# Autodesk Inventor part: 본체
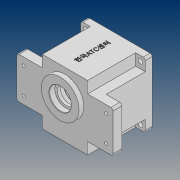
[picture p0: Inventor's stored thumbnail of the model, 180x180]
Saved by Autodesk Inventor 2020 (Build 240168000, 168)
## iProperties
Created: 2020-07
Part Number: 본체
Material: 일반
Document SubType Name: Modeling
Designer: PC312-
Density: 1 g/cm^3
Appearance: 기본값
Author: PC312-
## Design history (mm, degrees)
sketch "스케치1"
  geometry: L1 (-47, 47)-(47, 47); L2 (47, 47)-(47, -47); L3 (47, -47)-(-47, -47); L4 (-47, -47)-(-47, 47); L5 (-47, 47)-(47, -47); L6 (47, 47)-(-47, -47); 1 further point
  constraints: 12 end point, 2 midpoint, 2 parallel, 1 horizontal, 1 perpendicular
  dimensions: "d0" = 94 distance of L2.end L3.end; "d1" = 94 distance of L1.end L2.end
extrude "돌출1" new body sketch "스케치1" stored distance "d2" = 80; taper "d3" = 0 deg
sketch "스케치2"
  geometry: C1 r 27.5 at (0, 11); 1 further point
  constraints: 1 centre point, 1 vertical alignment
  dimensions: "d4" = 55 diameter of C1; "d5" = 11 distance of point (0, 0) C1.centre
extrude "돌출2" join sketch "스케치2" distance "d6" = 7; taper "d7" = 0 deg
sketch "스케치3"
  geometry: L1 (-70, 30)-(70, 30); L2 (70, 30)-(70, -30); L3 (70, -30)-(-70, -30); L4 (-70, -30)-(-70, 30); L5 (-70, 30)-(70, -30); L6 (70, 30)-(-70, -30); 1 further point
  constraints: 12 end point, 2 midpoint, 2 parallel, 1 horizontal, 1 perpendicular
  dimensions: "d8" = 140 distance of L2.end L3.end; "d9" = 60 distance of L1.end L2.end
extrude "돌출3" join sketch "스케치3" distance "d10" = 13; taper "d11" = 0 deg
sketch "스케치4"
  geometry: L1 (47, 47)-(-47, 47) reference; L2 (33, 47)-(33, 30); L3 (47, 30)-(47, -30) reference; L4 (33, 30)-(47, 30); L5 (47, 30)-(47, 47) reference; L6 (33, 47)-(47, 47); L7 (47, 47)-(47, 29.432); 1 further point
  constraints: 8 end point, 2 point on line, 1 horizontal, 1 vertical
  dimensions: "d12" = 17 distance of L2.start L2.end; "d14" = 14 distance of L2.end L3.start
extrude "돌출4" cut sketch "스케치4" distance "d15" = 70; taper "d16" = 0 deg
sketch "스케치5"
  geometry: C1 r 3.5 at (-40, -40); C2 r 3.5 at (40, -40); C3 r 3.5 at (-40, 40); C4 r 3.5 at (40, 40); 1 further point
  constraints: 4 centre point
  dimensions: "d17" = 7 diameter of C1; "d18" = 7 diameter of C2; "d19" = 7 diameter of C3; "d20" = 7 diameter of C4; "d21" = 80 distance of C2.centre C4.centre; "d22" = 80 distance of C1.centre C3.centre; "d23" = 80 distance of C4.centre C3.centre; "d24" = 80 distance of C2.centre C1.centre; "d25" = 40 horizontal distance of C4.centre point (0, 0); "d26" = 40 horizontal distance of point (0, 0) C3.centre; "d27" = 40 horizontal distance of C2.centre point (0, 0); "d28" = 40 horizontal distance of C2.centre point (0, 0)
extrude "돌출5" cut sketch "스케치5" extent not by distance; stored distance "d29" = 0; taper "d30" = 0 deg
sketch "스케치6"
  geometry: 3 further points
  constraints: 1 vertical alignment
  dimensions: "d31" = 38 distance of point (-60, 19) point (-60, -19); "d32" = 19 vertical distance of point (-60, -19) point (0, 0); "d33" = 60 horizontal distance of point (-60, -19) point (0, 0)
hole "구멍1" sketch "스케치6" at (-60, -19), (-60, 19) diameter "d34" = 4.5; stored, may be unused: countersink angle "d38" = 90 deg, drill point angle "d40" = 118 deg; dims "d35" = 8, "d36" = 10, "d37" = 5, "d39" = 13
sketch "스케치7"
  geometry: C1 r 43 at (0, 0); 1 further point
  constraints: 1 centre point, 1 coincident
  dimensions: "d41" = 86 diameter of C1
extrude "돌출6" cut sketch "스케치7" distance "d42" = 9; taper "d43" = 0 deg
sketch "스케치8"
  geometry: C1 r 40 at (0, 0); 1 further point
  constraints: 1 centre point, 1 coincident
  dimensions: "d44" = 80 diameter of C1
extrude "돌출7" cut sketch "스케치8" distance "d45" = 62; taper "d46" = 0 deg
sketch "스케치9"
  geometry: A1 r 21 centre (0, 11) between (12.163, -6.119) and (-12.163, -6.119); A2 r 15 centre (0, -20) between (-11.584, -10.47) and (11.584, -10.47); A3 r 3 centre (-13.901, -8.565) between (-11.584, -10.47) and (-12.163, -6.119); A4 r 3 centre (13.901, -8.565) between (12.163, -6.119) and (11.584, -10.47); 1 further point
  constraints: 8 point on circle, 4 centre point, 4 tangent, 2 vertical alignment
  dimensions: "d47" = 42 diameter of A1; "d48" = 30 diameter of A2; "d49" = 11 distance of point (0, 0) A1.centre; "d50" = 20 distance of point (0, 0) A2.centre; "d51" = 6 diameter of A3; "d52" = 6 diameter of A4
extrude "돌출8" join sketch "스케치9" distance "d53" = 7; taper "d54" = 0 deg
sketch "스케치10"
  geometry: A1 r 36 centre (0, 0) between (36, 0) and (-36, 0); A2 r 4 centre (36, 0) between (36.19, 3.995) and (36.19, -3.995); A3 r 4 centre (-36, 0) between (-36.19, -3.995) and (-36.19, 3.995); A4 r 3 centre (36.333, 6.992) between (35.772, 4.045) and (39.279, 7.559); A5 r 3 centre (36.333, -6.992) between (39.279, -7.559) and (35.772, -4.045); A6 r 3 centre (-36.333, 6.992) between (-39.279, 7.559) and (-35.772, 4.045); A7 r 3 centre (-36.333, -6.992) between (-35.772, -4.045) and (-39.279, -7.559); A8 r 40 centre (0, 0) between (-39.279, 7.559) and (-39.279, -7.559) reference; 1 further point
  constraints: 26 point on circle, 8 tangent, 7 centre point, 2 horizontal alignment, 1 coincident
  dimensions: "d55" = 72 diameter of A1; "d56" = 8 diameter of A2; "d57" = 8 diameter of A3; "d58" = 6 diameter of A4; "d59" = 6 diameter of A5; "d60" = 6 diameter of A6; "d61" = 6 diameter of A7
extrude "돌출9" join sketch "스케치10" distance "d62" = 62; taper "d63" = 0 deg
sketch "스케치11"
  geometry: C1 r 17.5 at (0, 11); A1 r 21 centre (0, 11) between (12.163, -6.119) and (-12.163, -6.119) reference; 1 further point
  constraints: 1 centre point, 1 coincident
  dimensions: "d64" = 35 diameter of C1
extrude "돌출10" cut sketch "스케치11" distance "d65" = 10; taper "d66" = 0 deg
sketch "스케치12"
  geometry: C1 r 27.5 at (0, 0) reference; 2 further points
  constraints: 1 coincident
hole "구멍2" sketch "스케치12" at (0, 0) diameter "d67" = 25; stored, may be unused: countersink angle "d71" = 90 deg, drill point angle "d73" = 118 deg; dims "d68" = 8, "d69" = 32, "d70" = 8.3, "d72" = 13
sketch "스케치13"
  geometry: C1 r 11 at (0, -20); A1 r 15 centre (0, -20) between (-11.584, -10.47) and (11.584, -10.47) reference; 1 further point
  constraints: 1 centre point, 1 coincident
  dimensions: "d74" = 22 diameter of C1
extrude "돌출11" cut sketch "스케치13" distance "d75" = 7; taper "d76" = 0 deg
sketch "스케치14"
  geometry: C1 r 9.5 at (0, 0); A1 r 15 centre (0, 0) between (-11.584, 9.53) and (11.584, 9.53) reference; 1 further point
  constraints: 1 centre point, 1 coincident
  dimensions: "d77" = 19 diameter of C1
extrude "돌출12" cut sketch "스케치14" distance "d78" = 3; taper "d79" = 0 deg
sketch "스케치16"
  geometry: A1 r 4 centre (36, 0) between (36.19, 3.995) and (36.19, -3.995) reference; A2 r 4 centre (-36, 0) between (-36.19, -3.995) and (-36.19, 3.995) reference; 3 further points
  constraints: 2 coincident
hole "구멍3" sketch "스케치16" at (36, 0), (-36, 0) diameter "d80" = 3.242; stored, may be unused: countersink angle "d84" = 90 deg, drill point angle "d86" = 118 deg; dims "d81" = 7, "d82" = 32, "d83" = 8.3, "d85" = 9
chamfer "모따기1" distance "d87" = 0.8; stored, may be unused: second distance "d88" = 2, angle "d89" = 30 deg
chamfer "모따기2" distance "d90" = 1; stored, may be unused: second distance "d91" = 2, angle "d92" = 30 deg
fillet "모깎기1" dims "d93" = 3
fillet "모깎기2" dims "d94" = 3
node "작업 평면1"
sketch "스케치17"
  geometry: L1 (-77, 80)-(11, 80) reference; 2 further points
  constraints: 1 coincident, 1 other
  dimensions: "d96" = 40 distance from line of L1 point (-33, 40)
feature "엠보싱1" sketch "스케치17" dims "d0" = 94, "d1" = 94, "d97" = 0.5, "d98" = 0
node "솔리드1"
mirror "미러1"
mirror "미러2"
mirror "미러3"
feature "A9D066F2-1C7D-4E18-AEED-F7BC21143FA4" dims "d34" = 4.5, "d35" = 8, "d36" = 10, "d37" = 5, "d38" = 90 deg, "d39" = 13, "d40" = 118 deg
other parameters: "d95" = 0.5
